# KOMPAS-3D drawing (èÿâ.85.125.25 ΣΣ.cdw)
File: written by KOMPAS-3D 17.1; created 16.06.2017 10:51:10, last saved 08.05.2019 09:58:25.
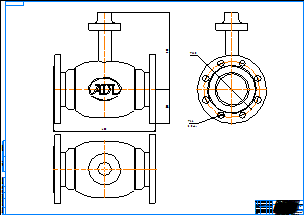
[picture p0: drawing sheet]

Sheet 1: A0, landscape

Title block, sheet 1: name: КШГ.85.125.25 фф; material: Внимание! Данный продукт является объектом авторского права ООО «Торговый Дом АДЛ». / Запрещается изменение, копирование, распространение / (в том числе путем копирования на другие сайты и ресурсы в Интернете) / или любое иное использование информации и объектов без предварительного / согласия правообладателя (ООО «Торговый Дом АДЛ»).; scale: 1:1; sheets: 1; organisation: ООО "Торговый дом АДЛ"; sheet format: A0; stored path: C:\Users\tra\Desktop\2д чертежи\Шаровые краны БИВАЛ\КШ_Бивал_серия_82_85\KOMPAS 2D\КШГ.85.125.25 фф.cdw

Views: Спереди 1, Проекционный вид 2, Проекционный вид 3
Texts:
  Klimkovich
  ADL
Dimensions and other numbers on the sheet: 400; 300; 135; 220; 26; 8 Отв.; 1:1; 1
